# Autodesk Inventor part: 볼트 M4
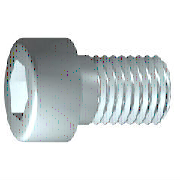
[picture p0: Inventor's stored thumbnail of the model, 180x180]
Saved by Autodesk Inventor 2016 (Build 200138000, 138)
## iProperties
IsCustomPart: 0
Created: 2012-02
Part Number: 볼트 M4
Material: 스테인리스강
Description: 6각 소켓 머리 캡 나사
Document SubType Name: Modeling
Standard: ISO 4762
Designer: mduedu
Standard Revision: Fourth edition 2004-03-01
Standards Organization: ISO
Language: ko-KR
Size Designation: M4 x 12
Categories: <MemberInstance><Categories><Category DisplayName="조임쇠" InternalName="e4da775c-781d-43d5-af7c-5136215cf5a6" Mnemonic="FSTN"><Category DisplayName="볼트" InternalN
Density: 8.08 g/cm^3
Mass: 2.2972 g
Surface Area: 3.30853 cm^2
Volume: 0.284306 cm^3
Appearance: 반광택
Author: mduedu
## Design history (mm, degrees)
sketch "스케치1"
  geometry: L1 (-1, 0)-(12, 0); L2 (12, 0)-(12, 2); L3 (12, 2)-(1.75, 2); L4 (1.75, 2)-(1.32, 2); L5 (1.32, 2)-(0, 2); L6 (0, 2)-(0, 3.5); L7 (0, 3.5)-(-4, 3.5); L8 (-4, 3.5)-(-4, 1.732); L9 (-4, 1.732)-(-2, 1.732); L10 (-2, 1.732)-(-1, 0); L11 (-7.2, 0)-(15.2, 0) reference; L12 (0, -0.7)-(0, 4.2) reference; L13 (1.75, 2)-(0, 2)
  constraints: 22 end point, 6 parallel, 2 collinear, 2 perpendicular, 1 horizontal, 1 point on line
  dimensions: "d1" = 10.25 distance from line of L3.end L2 (= GEL); "d2" = 0.42952 distance of L4.end L3.end (computed from GAL); "d3" = 4 distance between parallel lines of L8 L6 (= KOH); "d4" = 2 distance of L8.end L9.end (= INTI); "d5" = 60 deg angle of L10 L1; "d6" = 4 diameter of L3 L1 (= GD); "d7" = 4 diameter of L5 L1 (= BDM); "d8" = 3.4641 diameter of L9 L1 (= 1.1547 x SW); "d9" = 7 diameter of L7 L1 (= KOD); "d26" = 12 distance between parallel lines of L12 L2 (= NLG)
revolve "본체" sketch "스케치1" stored, may be unused: angle "d10" = 90 deg
sketch "스케치2"
  geometry: L1 (0, -4.9)-(0, 4.9) reference; L2 (-4.9, 0)-(4.9, 0) reference; L3 (1.732, 0)-(0.866, -1.5); L4 (0.866, -1.5)-(-0.866, -1.5); L5 (-0.866, -1.5)-(-1.732, 0); L6 (-1.732, 0)-(-0.866, 1.5); L7 (-0.866, 1.5)-(0.866, 1.5); L8 (0.866, 1.5)-(1.732, 0); 2 further points
  constraints: 12 end point, 1 coincident, 1 horizontal alignment, 1 point on line, 12 other
extrude "슬롯" join sketch "스케치2" stored distance "d11" = 10; taper "d12" = 0 deg
workplane "Work Plane1"
fillet "Fillet2" dims "d30" = 0.1 (= R)
body "Solid1"
fillet "모깎기1" dims "d17" = 0.4 (= RR)
feature "스레드" dims "d13" = 10.25 (= GEL), "d14" = 0
chamfer "모따기1" distance "d15" = 0.42941 (= -0.5 x SPD + 0.5 x GD); stored, may be unused: second distance "d16" = 0.42941 (= GUL), angle "d27" = 45 deg
other parameters: "GD" = 4 [user parameter; used in 2 equation terms], "NLG" = 12 [user parameter; used in 1 equation term], "GEL" = 10.25 [user parameter; used in 2 equation terms], "KOD" = 7 [user parameter; used in 1 equation term], "KOH" = 4 [user parameter; used in 1 equation term], "INTI" = 2 [user parameter; used in 1 equation term], "GAL" = 0.42941 (= 0.61345 x PTC) [user parameter; used in 1 equation term], "GUL" = 0.42941 (= 0.61345 x PTC) [user parameter; used in 1 equation term], "BDM" = 4 (= NND) [user parameter; used in 1 equation term], "SW" = 3 [user parameter; used in 2 equation terms], "RR" = 0.4 [user parameter; used in 1 equation term], "SPD" = 3.14117 (= NND - 1.2269 x PTC) [user parameter; used in 1 equation term], "d19" = 0, "d28" = 0, "d29" = 0, "R" = 0.1 [user parameter; used in 1 equation term], "TOA" = 30 deg [user parameter], "GD1" = 3.14117 (= THREADDIA - 1.2269 x PTC) [user parameter], "THREADDIA" = 4 [user parameter; used in 1 equation term], "FAWI" = 45 deg [user parameter], "TPU" = 14.28571 (computed from PTC) [user parameter], "PTC" = 0.7 [user parameter; used in 5 equation terms], "NND" = 4 [user parameter; used in 2 equation terms], "E0" = 3.465 (= 1.155 x SW) [user parameter]
